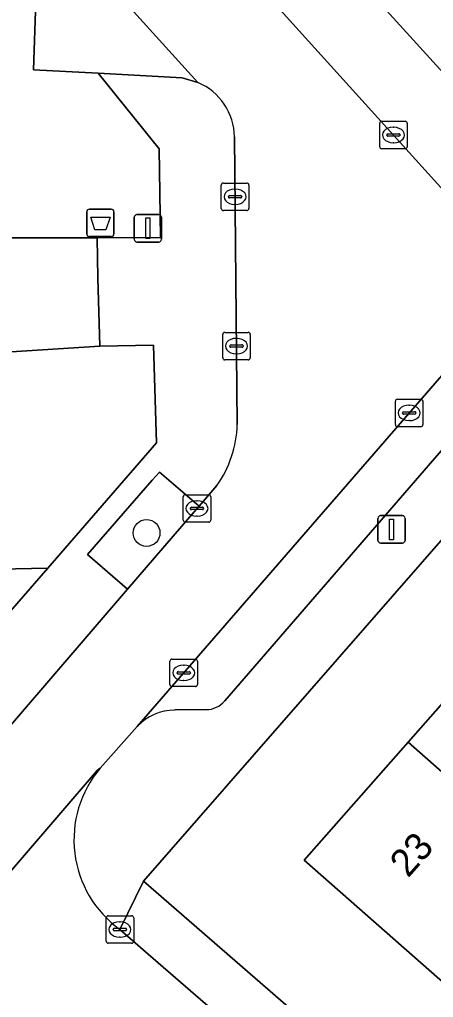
# Model space of a CAD drawing. Extents: x 158352 to 159489, y 383828 to 384603.
# Drawn here: x 159050.54 to 159065.59, y 384087.32 to 384122.89 of the extents above; entities that cross this region are included whole.
import ezdxf

# ---------------------------------------------------------------- set-up
doc = ezdxf.new("R2010")
doc.units = 0
for name, color, linetype in [('IMGEO_Afvalbak', 7, 'Continuous'), ('IMGEO_Boom', 7, 'Continuous'), ('IMGEO_Erf', 7, 'Continuous'), ('IMGEO_Groenvoorziening', 7, 'Continuous'), ('IMGEO_Kolk', 7, 'Continuous'), ('IMGEO_Lichtmast', 7, 'Continuous'), ('IMGEO_Pand', 7, 'Continuous'), ('IMGEO_Pand_nummerreeks', 7, 'Continuous'), ('IMGEO_Parkeervlak_open', 7, 'Continuous'), ('IMGEO_Rijbaan_lokaal_open', 7, 'Continuous'), ('IMGEO_Verkeersbordpaal', 7, 'Continuous'), ('IMGEO_Voetpad_gesloten', 7, 'Continuous'), ('IMGEO_Voetpad_open', 7, 'Continuous')]:
    doc.layers.add(name, color=color, linetype=linetype)

msp = doc.modelspace()

# ---------------------------------------------------------------- linework, layer by layer
at = {"layer": 'IMGEO_Afvalbak'}
for p, q in [((159052.98, 384115.089), (159052.98, 384115.889)), ((159052.98, 384115.889), (159052.98, 384115.089)), ((159053.08, 384115.989), (159053.87, 384115.989)), ((159053.87, 384115.989), (159053.08, 384115.989)), ((159053.97, 384115.889), (159053.97, 384115.089)), ((159053.97, 384115.089), (159053.97, 384115.889)), ((159053.87, 384114.989), (159053.08, 384114.989)), ((159053.08, 384114.989), (159053.87, 384114.989))]:
    msp.add_line(p, q, dxfattribs=at)
msp.add_lwpolyline([(159053.123, 384115.703), (159053.827, 384115.703), (159053.678, 384115.233), (159053.272, 384115.233), (159053.123, 384115.703)], dxfattribs=at)
for centre, start, end in [((159053.08, 384115.889), 90, 180), ((159053.08, 384115.889), 90, 180), ((159053.87, 384115.889), 0, 90), ((159053.87, 384115.889), 360, 90), ((159053.08, 384115.089), 180, 270), ((159053.08, 384115.089), 180, 270), ((159053.87, 384115.089), 270, 0), ((159053.87, 384115.089), 270, 0)]:
    msp.add_arc(centre, 0.1, start, end, dxfattribs=at)
at = {"layer": 'IMGEO_Boom'}
msp.add_circle((159055.153, 384104.213), 0.489, dxfattribs=at)
at = {"layer": 'IMGEO_Erf'}
for points in [[(159069.128, 384107.669), (159055.048, 384091.549), (159074.609, 384074.546)], [(159067.128, 384086.813), (159060.887, 384092.316), (159064.666, 384096.602), (159068.367, 384100.799)]]:
    msp.add_lwpolyline(points, dxfattribs=at)
at = {"layer": 'IMGEO_Groenvoorziening'}
msp.add_lwpolyline([(159049.948, 384114.946), (159053.362, 384114.944), (159055.66, 384114.955), (159055.614, 384118.187), (159053.394, 384120.931), (159051.046, 384121.062), (159051.127, 384123.555), (159048.63, 384123.703), (159048.742, 384126.212), (159046.196, 384126.338), (159046.36, 384128.831), (159043.798, 384129.019), (159043.962, 384131.512), (159041.417, 384131.637), (159041.515, 384134.173), (159039.063, 384134.297), (159039.2, 384136.685), (159034.505, 384141.891)], dxfattribs=at)
for points in [[(159055.521, 384107.485), (159055.404, 384111.037), (159053.457, 384111.01), (159048.699, 384110.702), (159047.273, 384110.45), (159045.173, 384108.768), (159035.173, 384097.214), (159038.743, 384094.084), (159046.256, 384102.828), (159051.561, 384102.933)], [(159056.801, 384104.884), (159057.063, 384105.189), (159055.624, 384106.427), (159055.362, 384106.127), (159053.004, 384103.425), (159054.462, 384102.165)], [(159041.649, 384091.536), (159051.561, 384102.933), (159046.256, 384102.828), (159038.743, 384094.084)]]:
    msp.add_lwpolyline(points, close=True, dxfattribs=at)
at = {"layer": 'IMGEO_Kolk'}
for p, q in [((159063.632, 384118.261), (159063.632, 384119.113)), ((159063.707, 384119.187), (159064.559, 384119.187)), ((159064.12, 384118.967), (159064.145, 384118.967)), ((159064.633, 384119.113), (159064.633, 384118.261)), ((159063.891, 384118.681), (159063.891, 384118.693)), ((159064.329, 384118.644), (159063.931, 384118.644)), ((159063.934, 384118.73), (159064.332, 384118.73)), ((159064.375, 384118.693), (159064.375, 384118.681)), ((159064.143, 384118.407), (159064.118, 384118.407)), ((159064.559, 384118.187), (159063.707, 384118.187)), ((159057.873, 384116.014), (159057.873, 384116.866)), ((159057.948, 384116.94), (159058.8, 384116.94)), ((159058.874, 384116.866), (159058.874, 384116.014)), ((159058.175, 384116.483), (159058.573, 384116.483)), ((159058.361, 384116.72), (159058.386, 384116.72)), ((159058.132, 384116.434), (159058.132, 384116.446)), ((159058.57, 384116.397), (159058.172, 384116.397)), ((159058.384, 384116.16), (159058.359, 384116.16)), ((159058.616, 384116.446), (159058.616, 384116.434)), ((159058.8, 384115.94), (159057.948, 384115.94)), ((159057.999, 384111.509), (159058.851, 384111.509)), ((159057.924, 384110.583), (159057.924, 384111.435)), ((159058.412, 384111.289), (159058.437, 384111.289)), ((159058.925, 384111.435), (159058.925, 384110.583)), ((159058.183, 384111.003), (159058.183, 384111.015)), ((159058.621, 384110.966), (159058.223, 384110.966)), ((159058.226, 384111.052), (159058.624, 384111.052)), ((159058.667, 384111.015), (159058.667, 384111.003)), ((159058.851, 384110.509), (159057.999, 384110.509)), ((159058.435, 384110.729), (159058.41, 384110.729)), ((159064.203, 384108.152), (159064.203, 384109.004)), ((159064.278, 384109.078), (159065.13, 384109.078)), ((159065.204, 384109.004), (159065.204, 384108.152)), ((159064.691, 384108.858), (159064.716, 384108.858)), ((159064.462, 384108.572), (159064.462, 384108.584)), ((159064.9, 384108.535), (159064.502, 384108.535)), ((159064.505, 384108.621), (159064.903, 384108.621)), ((159064.714, 384108.298), (159064.689, 384108.298)), ((159064.946, 384108.584), (159064.946, 384108.572)), ((159065.13, 384108.078), (159064.278, 384108.078)), ((159056.487, 384104.678), (159056.487, 384105.53)), ((159056.562, 384105.604), (159057.414, 384105.604)), ((159057.488, 384105.53), (159057.488, 384104.678)), ((159056.746, 384105.098), (159056.746, 384105.11)), ((159056.789, 384105.147), (159057.187, 384105.147)), ((159056.975, 384105.384), (159057, 384105.384)), ((159057.23, 384105.11), (159057.23, 384105.098)), ((159057.184, 384105.061), (159056.786, 384105.061)), ((159056.998, 384104.824), (159056.973, 384104.824)), ((159057.414, 384104.604), (159056.562, 384104.604)), ((159056.004, 384098.698), (159056.004, 384099.55)), ((159056.079, 384099.624), (159056.931, 384099.624)), ((159056.492, 384099.404), (159056.517, 384099.404)), ((159057.005, 384099.55), (159057.005, 384098.698)), ((159056.263, 384099.118), (159056.263, 384099.13)), ((159056.701, 384099.081), (159056.303, 384099.081)), ((159056.306, 384099.167), (159056.704, 384099.167)), ((159056.747, 384099.13), (159056.747, 384099.118)), ((159056.515, 384098.844), (159056.49, 384098.844)), ((159056.931, 384098.624), (159056.079, 384098.624)), ((159053.685, 384089.363), (159053.685, 384090.215)), ((159053.76, 384090.289), (159054.612, 384090.289)), ((159054.686, 384090.215), (159054.686, 384089.363)), ((159053.944, 384089.783), (159053.944, 384089.795)), ((159053.987, 384089.832), (159054.385, 384089.832)), ((159054.173, 384090.069), (159054.198, 384090.069)), ((159054.428, 384089.795), (159054.428, 384089.783)), ((159054.382, 384089.746), (159053.984, 384089.746)), ((159054.196, 384089.509), (159054.171, 384089.509)), ((159054.612, 384089.289), (159053.76, 384089.289))]:
    msp.add_line(p, q, dxfattribs=at)
for points in [[(159063.632, 384118.261), (159063.632, 384119.113)], [(159063.707, 384119.187), (159064.559, 384119.187)], [(159064.633, 384119.113), (159064.633, 384118.261)], [(159064.559, 384118.187), (159063.707, 384118.187)], [(159057.873, 384116.014), (159057.873, 384116.866)], [(159057.948, 384116.94), (159058.8, 384116.94)], [(159058.874, 384116.866), (159058.874, 384116.014)], [(159058.8, 384115.94), (159057.948, 384115.94)], [(159057.999, 384111.509), (159058.851, 384111.509)], [(159057.924, 384110.583), (159057.924, 384111.435)], [(159058.925, 384111.435), (159058.925, 384110.583)], [(159058.851, 384110.509), (159057.999, 384110.509)], [(159064.203, 384108.152), (159064.203, 384109.004)], [(159064.278, 384109.078), (159065.13, 384109.078)], [(159065.204, 384109.004), (159065.204, 384108.152)], [(159065.13, 384108.078), (159064.278, 384108.078)], [(159056.487, 384104.678), (159056.487, 384105.53)], [(159056.562, 384105.604), (159057.414, 384105.604)], [(159057.488, 384105.53), (159057.488, 384104.678)], [(159057.414, 384104.604), (159056.562, 384104.604)], [(159056.004, 384098.698), (159056.004, 384099.55)], [(159056.079, 384099.624), (159056.931, 384099.624)], [(159057.005, 384099.55), (159057.005, 384098.698)], [(159056.931, 384098.624), (159056.079, 384098.624)], [(159053.685, 384089.363), (159053.685, 384090.215)], [(159053.76, 384090.289), (159054.612, 384090.289)], [(159054.686, 384090.215), (159054.686, 384089.363)], [(159054.612, 384089.289), (159053.76, 384089.289)]]:
    msp.add_lwpolyline(points, dxfattribs=at)
for centre, radius, start, end in [((159063.709, 384119.111), 0.0765, 91.552, 178.448), ((159063.709, 384119.111), 0.0765, 91.552, 178.448), ((159064.557, 384119.111), 0.0765, 1.552, 88.448), ((159064.557, 384119.111), 0.0765, 1.552, 88.448), ((159063.931, 384118.69), 0.0403, 85.8775, 175.7526), ((159063.928, 384118.68), 0.0366, 178.938, 274.7102), ((159064.332, 384118.687), 0.043, 264.8664, 352.4533), ((159064.336, 384118.692), 0.0386, 1.7309, 96.639), ((159063.709, 384118.263), 0.0765, 181.552, 268.448), ((159063.709, 384118.263), 0.0765, 181.552, 268.448), ((159064.557, 384118.263), 0.0765, 271.552, 358.448), ((159064.557, 384118.263), 0.0765, 271.552, 358.448), ((159057.95, 384116.864), 0.0765, 91.552, 178.448), ((159057.95, 384116.864), 0.0765, 91.552, 178.448), ((159058.798, 384116.864), 0.0765, 1.552, 88.448), ((159058.798, 384116.864), 0.0765, 1.552, 88.448), ((159058.172, 384116.443), 0.0403, 85.8775, 175.7526), ((159058.577, 384116.445), 0.0386, 1.7309, 96.639), ((159058.169, 384116.433), 0.0366, 178.938, 274.7102), ((159058.573, 384116.44), 0.043, 264.8664, 352.4533), ((159057.95, 384116.016), 0.0765, 181.552, 268.448), ((159057.95, 384116.016), 0.0765, 181.552, 268.448), ((159058.798, 384116.016), 0.0765, 271.552, 358.448), ((159058.798, 384116.016), 0.0765, 271.552, 358.448), ((159058.001, 384111.433), 0.0765, 91.552, 178.448), ((159058.001, 384111.433), 0.0765, 91.552, 178.448), ((159058.849, 384111.433), 0.0765, 1.552, 88.448), ((159058.849, 384111.433), 0.0765, 1.552, 88.448), ((159058.223, 384111.012), 0.0403, 85.8775, 175.7526), ((159058.22, 384111.002), 0.0366, 178.938, 274.7102), ((159058.624, 384111.009), 0.043, 264.8664, 352.4533), ((159058.628, 384111.014), 0.0386, 1.7309, 96.639), ((159058.001, 384110.585), 0.0765, 181.552, 268.448), ((159058.001, 384110.585), 0.0765, 181.552, 268.448), ((159058.849, 384110.585), 0.0765, 271.552, 358.448), ((159058.849, 384110.585), 0.0765, 271.552, 358.448), ((159064.28, 384109.002), 0.0765, 91.552, 178.448), ((159064.28, 384109.002), 0.0765, 91.552, 178.448), ((159065.128, 384109.002), 0.0765, 1.552, 88.448), ((159065.128, 384109.002), 0.0765, 1.552, 88.448), ((159064.502, 384108.581), 0.0403, 85.8775, 175.7526), ((159064.499, 384108.571), 0.0366, 178.938, 274.7102), ((159064.903, 384108.578), 0.043, 264.8664, 352.4533), ((159064.907, 384108.583), 0.0386, 1.7309, 96.639), ((159064.28, 384108.154), 0.0765, 181.552, 268.448), ((159064.28, 384108.154), 0.0765, 181.552, 268.448), ((159065.128, 384108.154), 0.0765, 271.552, 358.448), ((159065.128, 384108.154), 0.0765, 271.552, 358.448), ((159056.564, 384105.528), 0.0765, 91.552, 178.448), ((159056.564, 384105.528), 0.0765, 91.552, 178.448), ((159057.412, 384105.528), 0.0765, 1.552, 88.448), ((159057.412, 384105.528), 0.0765, 1.552, 88.448), ((159056.786, 384105.107), 0.0403, 85.8775, 175.7526), ((159056.783, 384105.097), 0.0366, 178.938, 274.7102), ((159057.187, 384105.104), 0.043, 264.8664, 352.4533), ((159057.191, 384105.109), 0.0386, 1.7309, 96.639), ((159056.564, 384104.68), 0.0765, 181.552, 268.448), ((159056.564, 384104.68), 0.0765, 181.552, 268.448), ((159057.412, 384104.68), 0.0765, 271.552, 358.448), ((159057.412, 384104.68), 0.0765, 271.552, 358.448), ((159056.081, 384099.548), 0.0765, 91.552, 178.448), ((159056.081, 384099.548), 0.0765, 91.552, 178.448), ((159056.929, 384099.548), 0.0765, 1.552, 88.448), ((159056.929, 384099.548), 0.0765, 1.552, 88.448), ((159056.303, 384099.127), 0.0403, 85.8775, 175.7526), ((159056.3, 384099.117), 0.0366, 178.938, 274.7102), ((159056.704, 384099.124), 0.043, 264.8664, 352.4533), ((159056.708, 384099.129), 0.0386, 1.7309, 96.639), ((159056.081, 384098.7), 0.0765, 181.552, 268.448), ((159056.081, 384098.7), 0.0765, 181.552, 268.448), ((159056.929, 384098.7), 0.0765, 271.552, 358.448), ((159056.929, 384098.7), 0.0765, 271.552, 358.448), ((159053.762, 384090.213), 0.0765, 91.552, 178.448), ((159053.762, 384090.213), 0.0765, 91.552, 178.448), ((159054.61, 384090.213), 0.0765, 1.552, 88.448), ((159054.61, 384090.213), 0.0765, 1.552, 88.448), ((159053.984, 384089.792), 0.0403, 85.8775, 175.7526), ((159053.981, 384089.782), 0.0366, 178.938, 274.7102), ((159054.385, 384089.789), 0.043, 264.8664, 352.4533), ((159054.389, 384089.794), 0.0386, 1.7309, 96.639), ((159053.762, 384089.365), 0.0765, 181.552, 268.448), ((159053.762, 384089.365), 0.0765, 181.552, 268.448), ((159054.61, 384089.365), 0.0765, 271.552, 358.448), ((159054.61, 384089.365), 0.0765, 271.552, 358.448)]:
    msp.add_arc(centre, radius, start, end, dxfattribs=at)
for centre, major_axis, ratio, start_param, end_param in [((159064.119, 384118.687), (-0.387, 0.002), 0.722429, 4.712389, 7.853982), ((159064.144, 384118.687), (-0.39, 0.002), 0.717154, 1.570796, 4.712389), ((159058.36, 384116.44), (-0.387, 0.002), 0.722429, 4.712389, 7.853982), ((159058.385, 384116.44), (-0.39, 0.002), 0.717154, 1.570796, 4.712389), ((159058.411, 384111.009), (-0.387, 0.002), 0.722429, 4.712389, 7.853982), ((159058.436, 384111.009), (-0.39, 0.002), 0.717154, 1.570796, 4.712389), ((159064.69, 384108.578), (-0.387, 0.002), 0.722429, 4.712389, 7.853982), ((159064.715, 384108.578), (-0.39, 0.002), 0.717154, 1.570796, 4.712389), ((159056.974, 384105.104), (-0.387, 0.002), 0.722429, 4.712389, 7.853982), ((159056.999, 384105.104), (-0.39, 0.002), 0.717154, 1.570796, 4.712389), ((159056.491, 384099.124), (-0.387, 0.002), 0.722429, 4.712389, 7.853982), ((159056.516, 384099.124), (-0.39, 0.002), 0.717154, 1.570796, 4.712389), ((159054.172, 384089.789), (-0.387, 0.002), 0.722429, 4.712389, 7.853982), ((159054.197, 384089.789), (-0.39, 0.002), 0.717154, 1.570796, 4.712389)]:
    msp.add_ellipse(centre, major_axis=major_axis, ratio=ratio, start_param=start_param, end_param=end_param, dxfattribs=at)
at = {"layer": 'IMGEO_Lichtmast'}
for p, q in [((159063.567, 384103.942), (159063.567, 384104.742)), ((159063.567, 384104.742), (159063.567, 384103.942)), ((159063.667, 384104.842), (159064.457, 384104.842)), ((159064.457, 384104.842), (159063.667, 384104.842)), ((159064.557, 384104.742), (159064.557, 384103.942)), ((159064.557, 384103.942), (159064.557, 384104.742)), ((159064.457, 384103.842), (159063.667, 384103.842)), ((159063.667, 384103.842), (159064.457, 384103.842))]:
    msp.add_line(p, q, dxfattribs=at)
msp.add_lwpolyline([(159063.987, 384104.717), (159064.137, 384104.717), (159064.137, 384103.967), (159063.987, 384103.967), (159063.987, 384104.717)], dxfattribs=at)
for centre, start, end in [((159063.667, 384104.742), 90, 180), ((159063.667, 384104.742), 90, 180), ((159064.457, 384104.742), 0, 90), ((159064.457, 384104.742), 360, 90), ((159063.667, 384103.942), 180, 270), ((159063.667, 384103.942), 180, 270), ((159064.457, 384103.942), 270, 0), ((159064.457, 384103.942), 270, 0)]:
    msp.add_arc(centre, 0.1, start, end, dxfattribs=at)
at = {"layer": 'IMGEO_Pand'}
for points in [[(159062.912, 384124.289), (159066.787, 384120.01), (159072.056, 384124.782), (159071.812, 384125.051), (159076.437, 384129.24), (159076.363, 384129.322), (159073.08, 384132.945), (159072.802, 384133.248)], [(159074.206, 384088.186), (159075.734, 384089.92), (159076.164, 384090.407), (159073.043, 384093.16), (159074.786, 384095.136), (159074.515, 384095.375), (159068.367, 384100.799), (159064.666, 384096.602)], [(159074.206, 384088.186), (159064.666, 384096.602), (159060.887, 384092.316), (159067.128, 384086.813), (159069.126, 384089.079), (159072.427, 384086.169)]]:
    msp.add_lwpolyline(points, close=True, dxfattribs=at)
at = {"layer": 'IMGEO_Parkeervlak_open'}
for points in [[(159041.411, 384136.563), (159039.2, 384136.685), (159039.063, 384134.297), (159041.515, 384134.173), (159041.417, 384131.637), (159043.962, 384131.512), (159043.798, 384129.019), (159046.36, 384128.831), (159046.196, 384126.338), (159048.742, 384126.212), (159048.63, 384123.703), (159051.127, 384123.555), (159051.046, 384121.062), (159053.394, 384120.931), (159056.45, 384120.76), (159057.024, 384120.599), (159041.806, 384137.388)], [(159068.076, 384110.141), (159068.096, 384112.115), (159068.118, 384112.515), (159054.813, 384097.177)], [(159058.002, 384098.104), (159067.815, 384109.452)], [(159056.179, 384097.773), (159057.317, 384097.786)]]:
    msp.add_lwpolyline(points, dxfattribs=at)
for centre, radius, start, end in [((159057.309, 384098.7), 0.914, 270.5007, 319.3039), ((159056.208, 384095.842), 1.931, 90.8744, 136.2699)]:
    msp.add_arc(centre, radius, start, end, dxfattribs=at)
at = {"layer": 'IMGEO_Rijbaan_lokaal_open'}
for points in [[(159068.743, 384113.557), (159065.968, 384116.658), (159044.215, 384140.706), (159041.241, 384138.016), (159041.806, 384137.388), (159057.024, 384120.599)], [(159058.355, 384118.618), (159058.452, 384108.157)], [(159038.219, 384077.693), (159044.89, 384085.714), (159044.934, 384085.755), (159046.34, 384087.391), (159046.376, 384087.444), (159053.358, 384095.568), (159053.473, 384095.66), (159054.813, 384097.177), (159068.118, 384112.515)], [(159057.711, 384105.943), (159057.063, 384105.189), (159056.801, 384104.884), (159054.462, 384102.165), (159047.772, 384094.384), (159045.79, 384092.078), (159042.871, 384088.683), (159040.059, 384085.439), (159038.288, 384083.396), (159031.77, 384075.877), (159029.982, 384073.814), (159029.242, 384072.961)], [(159053.473, 384095.66), (159053.358, 384095.568), (159046.376, 384087.444), (159046.34, 384087.391)], [(159055.21, 384088.896), (159054.182, 384089.791)], [(159049.223, 384087.62), (159049.651, 384087.245), (159050.8, 384086.238), (159080.25, 384060.43), (159085.805, 384055.65), (159089.071, 384059.415), (159073.221, 384073.303), (159070.333, 384075.803), (159055.21, 384088.896)]]:
    msp.add_lwpolyline(points, dxfattribs=at)
for centre, radius, start, end in [((159056.144, 384118.57), 2.211, 1.2387, 66.5542), ((159054.507, 384108.246), 3.946, 324.2887, 358.7017), ((159056.534, 384093.052), 4.021, 139.5744, 234.202)]:
    msp.add_arc(centre, radius, start, end, dxfattribs=at)
at = {"layer": 'IMGEO_Verkeersbordpaal'}
for p, q in [((159054.806, 384115.794), (159055.596, 384115.794)), ((159055.596, 384115.794), (159054.806, 384115.794)), ((159054.706, 384114.894), (159054.706, 384115.694)), ((159054.706, 384115.694), (159054.706, 384114.894)), ((159055.696, 384115.694), (159055.696, 384114.894)), ((159055.696, 384114.894), (159055.696, 384115.694)), ((159055.596, 384114.794), (159054.806, 384114.794)), ((159054.806, 384114.794), (159055.596, 384114.794))]:
    msp.add_line(p, q, dxfattribs=at)
msp.add_lwpolyline([(159055.126, 384115.669), (159055.276, 384115.669), (159055.276, 384114.919), (159055.126, 384114.919), (159055.126, 384115.669)], dxfattribs=at)
for centre, start, end in [((159054.806, 384115.694), 90, 180), ((159054.806, 384115.694), 90, 180), ((159055.596, 384115.694), 0, 90), ((159055.596, 384115.694), 360, 90), ((159054.806, 384114.894), 180, 270), ((159054.806, 384114.894), 180, 270), ((159055.596, 384114.894), 270, 0), ((159055.596, 384114.894), 270, 0)]:
    msp.add_arc(centre, 0.1, start, end, dxfattribs=at)
at = {"layer": 'IMGEO_Voetpad_gesloten'}
msp.add_lwpolyline([(159045.173, 384108.768), (159047.273, 384110.45), (159048.699, 384110.702), (159053.457, 384111.01), (159053.387, 384113.488), (159053.362, 384114.944), (159049.948, 384114.946)], dxfattribs=at)
at = {"layer": 'IMGEO_Voetpad_open'}
for points in [[(159000, 384189.555), (159006.524, 384182.375), (159021.065, 384166.299), (159023.125, 384164.023), (159042.135, 384143.006), (159044.215, 384140.706), (159065.968, 384116.658)], [(159066.787, 384120.01), (159062.912, 384124.289)], [(159057.024, 384120.599), (159056.45, 384120.76), (159053.394, 384120.931), (159055.614, 384118.187), (159055.66, 384114.955), (159053.362, 384114.944), (159053.387, 384113.488), (159053.457, 384111.01), (159055.404, 384111.037), (159055.521, 384107.485), (159051.561, 384102.933), (159041.649, 384091.536), (159040.473, 384090.185), (159039.9, 384089.519), (159029.037, 384076.903), (159026.653, 384074.134), (159024.169, 384073.744), (159023.773, 384075.803), (159019.929, 384075.142)], [(159058.452, 384108.157), (159058.355, 384118.618)], [(159067.815, 384109.452), (159058.002, 384098.104)], [(159054.182, 384089.791), (159055.048, 384091.549), (159069.128, 384107.669)], [(159029.242, 384072.961), (159029.982, 384073.814), (159028.736, 384074.896), (159030.496, 384076.945), (159031.77, 384075.877), (159038.288, 384083.396), (159037.079, 384084.4), (159038.787, 384086.531), (159040.059, 384085.439), (159042.871, 384088.683), (159045.79, 384092.078), (159044.423, 384093.312), (159046.39, 384095.578), (159047.772, 384094.384), (159054.462, 384102.165), (159053.004, 384103.425), (159055.362, 384106.127), (159055.624, 384106.427), (159057.063, 384105.189), (159057.711, 384105.943)], [(159057.317, 384097.786), (159056.179, 384097.773)], [(159054.813, 384097.177), (159053.473, 384095.66)]]:
    msp.add_lwpolyline(points, dxfattribs=at)
msp.add_lwpolyline([(159075.619, 384073.668), (159074.609, 384074.546), (159055.048, 384091.549), (159054.182, 384089.791), (159055.21, 384088.896), (159070.333, 384075.803), (159073.221, 384073.303), (159089.071, 384059.415), (159093.849, 384055.229), (159098.324, 384051.355), (159099.594, 384052.806), (159096.403, 384055.601)], close=True, dxfattribs=at)
for centre, radius, start, end in [((159056.144, 384118.57), 2.211, 1.2387, 66.5542), ((159054.507, 384108.246), 3.946, 324.2887, 358.7017), ((159057.309, 384098.7), 0.914, 270.5007, 319.3039), ((159056.208, 384095.842), 1.931, 90.8744, 136.2699), ((159056.534, 384093.052), 4.021, 139.5744, 234.202)]:
    msp.add_arc(centre, radius, start, end, dxfattribs=at)

# ---------------------------------------------------------------- texts
at = {"layer": 'IMGEO_Pand_nummerreeks'}
msp.add_text('23', height=1, rotation=48.5877, dxfattribs=at).set_placement((159064.665, 384091.64))

doc.saveas('drawing.dxf')
